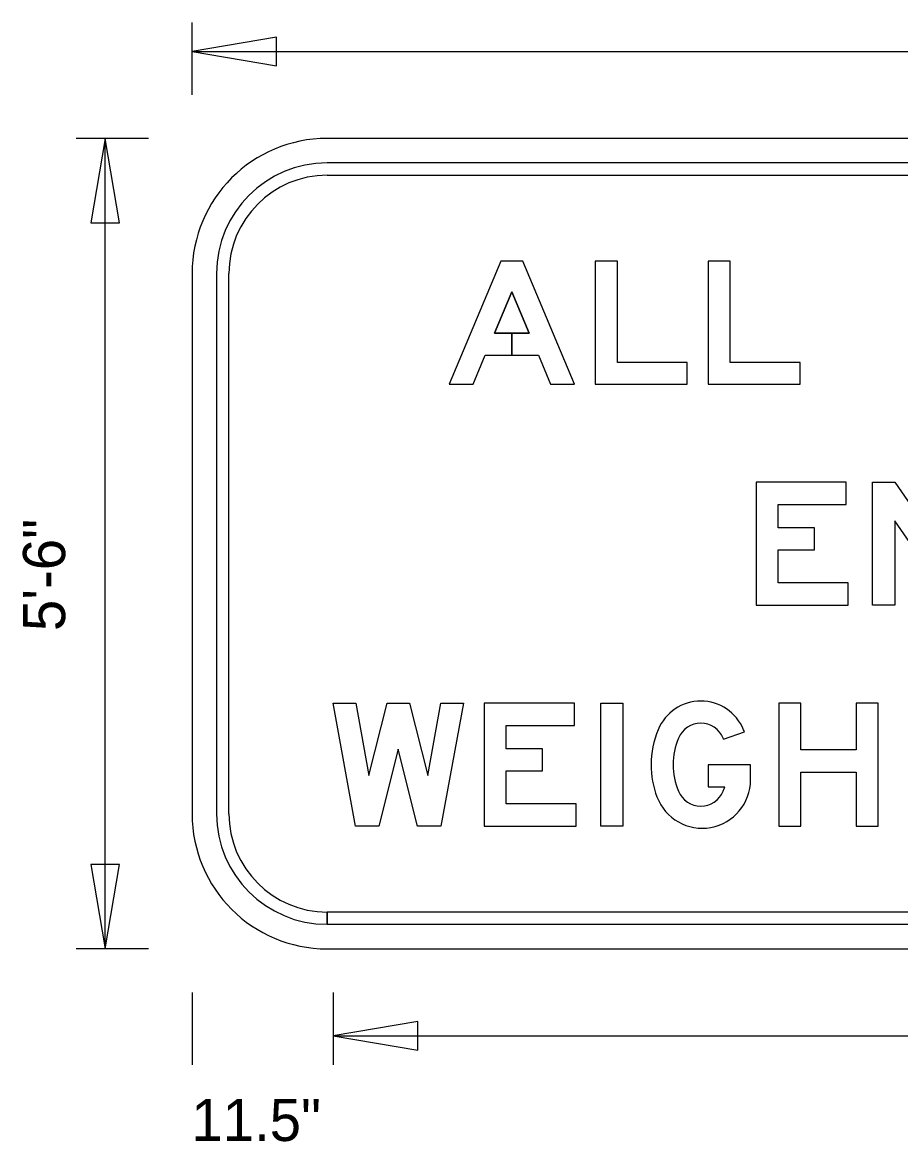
# Model space of a CAD drawing. Extents: x 0 to 770, y 0 to 495.
# Drawn here: x 7.2 to 80.1, y 381.9 to 474.8 of the extents above; entities that cross this region are included whole.
import ezdxf

# ---------------------------------------------------------------- set-up
doc = ezdxf.new("R2010")
doc.units = 0
for name, color, linetype in [('Dimension', 7, 'Continuous'), ('GSBWFill', 7, 'Continuous'), ('GSColorFill', 7, 'Continuous'), ('GSDims', 7, 'Continuous'), ('GSOutline', 7, 'Continuous'), ('TextStructures', 7, 'Continuous')]:
    doc.layers.add(name, color=color, linetype=linetype)

msp = doc.modelspace()

# ---------------------------------------------------------------- linework, layer by layer
at = {"layer": 'Dimension'}
for points in [[(21.25, 472.405), (28.266, 471.216), (28.266, 473.594)], [(14.025, 465.181), (12.837, 458.164), (15.214, 458.164)], [(14.025, 397.907), (15.214, 404.924), (12.837, 404.924)], [(32.972, 390.683), (39.988, 389.494), (39.988, 391.871)]]:
    msp.add_lwpolyline(points, close=True, dxfattribs=at)
at = {"layer": 'GSBWFill'}
for p, q in [((150.701, 465.181), (32.462, 465.181)), ((150.701, 463.142), (32.462, 463.142)), ((32.462, 462.123), (150.701, 462.123)), ((21.25, 453.969), (21.25, 409.119)), ((23.288, 453.969), (23.288, 409.119)), ((24.308, 409.119), (24.308, 453.969)), ((65.393, 415.305), (67.121, 415.923)), ((67.628, 411.935), (67.628, 413.196)), ((32.462, 399.946), (32.462, 400.965)), ((150.701, 400.965), (32.472, 400.965)), ((32.472, 400.965), (32.472, 399.946)), ((32.472, 399.946), (150.701, 399.946)), ((32.462, 397.907), (150.701, 397.907))]:
    msp.add_line(p, q, dxfattribs=at)
for points in [[(49.234, 449.025), (47.803, 449.025), (47.803, 447.19), (50.005, 447.19), (51.011, 444.795), (53.001, 444.795), (48.72, 454.988), (46.885, 454.988), (42.604, 444.795), (44.594, 444.795), (45.6, 447.19), (47.802, 447.19), (47.802, 449.025), (46.371, 449.025), (47.802, 452.434)], [(62.378, 444.795), (62.378, 446.579), (56.568, 446.579), (56.568, 454.988), (54.734, 454.988), (54.734, 444.795)], [(71.756, 444.795), (71.756, 446.579), (65.946, 446.579), (65.946, 454.988), (64.111, 454.988), (64.111, 444.795)], [(75.731, 428.282), (69.921, 428.282), (69.921, 431.024), (72.928, 431.024), (72.928, 432.859), (69.921, 432.859), (69.921, 434.806), (75.578, 434.806), (75.578, 436.64), (68.087, 436.64), (68.087, 426.447), (75.731, 426.447)], [(86.026, 436.64), (86.026, 426.447), (84.446, 426.447), (79.605, 433.43), (79.605, 426.447), (77.77, 426.447), (77.77, 436.64), (79.611, 436.64), (84.192, 430.035), (84.192, 436.64)], [(38.374, 414.471), (36.768, 408.1), (34.832, 408.1), (32.972, 418.293), (34.837, 418.293), (35.932, 412.29), (37.445, 418.293), (39.303, 418.293), (40.816, 412.29), (41.911, 418.293), (43.776, 418.293), (41.916, 408.1), (39.979, 408.1)], [(53.154, 409.935), (47.344, 409.935), (47.344, 412.676), (50.351, 412.676), (50.351, 414.511), (47.344, 414.511), (47.344, 416.458), (53.001, 416.458), (53.001, 418.293), (45.509, 418.293), (45.509, 408.1), (53.154, 408.1)], [(55.192, 408.1), (55.192, 418.293), (57.027, 418.293), (57.027, 408.1)], [(76.394, 414.42), (71.807, 414.42), (71.807, 418.293), (69.972, 418.293), (69.972, 408.1), (71.807, 408.1), (71.807, 412.585), (76.394, 412.585), (76.394, 408.1), (78.229, 408.1), (78.229, 418.293), (76.394, 418.293)]]:
    msp.add_lwpolyline(points, close=True, dxfattribs=at)
msp.add_lwpolyline([(67.628, 413.196), (64.111, 413.196), (64.111, 411.362), (65.493, 411.362)], dxfattribs=at)
for centre, radius, start, end in [((32.462, 453.969), 11.212, 90, 180), ((32.462, 453.969), 9.174, 90, 180), ((32.462, 453.969), 8.154, 90, 180), ((32.462, 409.119), 11.212, 180, 270), ((32.462, 409.119), 9.174, 180, 270), ((32.462, 409.119), 8.154, 180, 270)]:
    msp.add_arc(centre, radius, start, end, dxfattribs=at)
for centre, major_axis, start_param, end_param in [((63.5, 414.627), (0, 3.845), 5.10379, 7.46258), ((63.5, 414.627), (0, 2.01), 5.10379, 7.46258), ((66.965, 413.196), (0, 7.594), 1.179395, 1.570796), ((66.965, 413.196), (0, 5.759), 1.179395, 1.570796), ((60.034, 413.196), (0, 5.759), 5.087148, 5.10379), ((60.034, 413.196), (0, 7.594), 5.07965, 5.10379), ((66.965, 413.196), (0, 7.594), 1.570796, 1.930863), ((66.965, 413.196), (0, 5.759), 1.570796, 1.962198), ((63.614, 411.935), (0, 4.013), 1.930863, 4.712389), ((63.5, 411.766), (0, 2.01), 1.962198, 4.320988), ((60.034, 413.196), (0, 5.759), 4.320988, 4.388154)]:
    msp.add_ellipse(centre, major_axis=major_axis, ratio=0.999994, start_param=start_param, end_param=end_param, dxfattribs=at)
at = {"layer": 'GSColorFill'}
for p, q in [((65.393, 415.305), (67.121, 415.923)), ((67.628, 411.935), (67.628, 413.196))]:
    msp.add_line(p, q, dxfattribs=at)
for points in [[(49.234, 449.025), (47.803, 449.025), (47.803, 447.19), (50.005, 447.19), (51.011, 444.795), (53.001, 444.795), (48.72, 454.988), (46.885, 454.988), (42.604, 444.795), (44.594, 444.795), (45.6, 447.19), (47.802, 447.19), (47.802, 449.025), (46.371, 449.025), (47.802, 452.434)], [(62.378, 444.795), (62.378, 446.579), (56.568, 446.579), (56.568, 454.988), (54.734, 454.988), (54.734, 444.795)], [(71.756, 444.795), (71.756, 446.579), (65.946, 446.579), (65.946, 454.988), (64.111, 454.988), (64.111, 444.795)], [(75.731, 428.282), (69.921, 428.282), (69.921, 431.024), (72.928, 431.024), (72.928, 432.859), (69.921, 432.859), (69.921, 434.806), (75.578, 434.806), (75.578, 436.64), (68.087, 436.64), (68.087, 426.447), (75.731, 426.447)], [(86.026, 436.64), (86.026, 426.447), (84.446, 426.447), (79.605, 433.43), (79.605, 426.447), (77.77, 426.447), (77.77, 436.64), (79.611, 436.64), (84.192, 430.035), (84.192, 436.64)], [(38.374, 414.471), (36.768, 408.1), (34.832, 408.1), (32.972, 418.293), (34.837, 418.293), (35.932, 412.29), (37.445, 418.293), (39.303, 418.293), (40.816, 412.29), (41.911, 418.293), (43.776, 418.293), (41.916, 408.1), (39.979, 408.1)], [(53.154, 409.935), (47.344, 409.935), (47.344, 412.676), (50.351, 412.676), (50.351, 414.511), (47.344, 414.511), (47.344, 416.458), (53.001, 416.458), (53.001, 418.293), (45.509, 418.293), (45.509, 408.1), (53.154, 408.1)], [(55.192, 408.1), (55.192, 418.293), (57.027, 418.293), (57.027, 408.1)], [(76.394, 414.42), (71.807, 414.42), (71.807, 418.293), (69.972, 418.293), (69.972, 408.1), (71.807, 408.1), (71.807, 412.585), (76.394, 412.585), (76.394, 408.1), (78.229, 408.1), (78.229, 418.293), (76.394, 418.293)]]:
    msp.add_lwpolyline(points, close=True, dxfattribs=at)
msp.add_lwpolyline([(67.628, 413.196), (64.111, 413.196), (64.111, 411.362), (65.493, 411.362)], dxfattribs=at)
for centre, major_axis, start_param, end_param in [((63.5, 414.627), (0, 3.845), 5.10379, 7.46258), ((63.5, 414.627), (0, 2.01), 5.10379, 7.46258), ((66.965, 413.196), (0, 7.594), 1.179395, 1.570796), ((66.965, 413.196), (0, 5.759), 1.179395, 1.570796), ((60.034, 413.196), (0, 5.759), 5.087148, 5.10379), ((60.034, 413.196), (0, 7.594), 5.07965, 5.10379), ((66.965, 413.196), (0, 7.594), 1.570796, 1.930863), ((66.965, 413.196), (0, 5.759), 1.570796, 1.962198), ((63.614, 411.935), (0, 4.013), 1.930863, 4.712389), ((63.5, 411.766), (0, 2.01), 1.962198, 4.320988), ((60.034, 413.196), (0, 5.759), 4.320988, 4.388154)]:
    msp.add_ellipse(centre, major_axis=major_axis, ratio=0.999994, start_param=start_param, end_param=end_param, dxfattribs=at)
at = {"layer": 'GSDims'}
for p, q in [((21.25, 468.793), (21.25, 474.813)), ((21.25, 472.405), (161.913, 472.405)), ((17.637, 465.181), (11.617, 465.181)), ((14.025, 397.907), (14.025, 465.181)), ((17.637, 397.907), (11.617, 397.907)), ((21.25, 394.295), (21.25, 388.275)), ((32.972, 394.295), (32.972, 388.275)), ((32.972, 394.295), (32.972, 388.275)), ((32.972, 390.683), (150.191, 390.683))]:
    msp.add_line(p, q, dxfattribs=at)
at = {"layer": 'GSOutline'}
for p, q in [((65.393, 415.305), (67.121, 415.923)), ((67.628, 411.935), (67.628, 413.196))]:
    msp.add_line(p, q, dxfattribs=at)
for points in [[(45.6, 447.19), (50.005, 447.19), (51.011, 444.795), (53.001, 444.795), (48.72, 454.988), (46.885, 454.988), (42.604, 444.795), (44.594, 444.795)], [(62.378, 444.795), (62.378, 446.579), (56.568, 446.579), (56.568, 454.988), (54.734, 454.988), (54.734, 444.795)], [(71.756, 444.795), (71.756, 446.579), (65.946, 446.579), (65.946, 454.988), (64.111, 454.988), (64.111, 444.795)], [(49.234, 449.025), (47.802, 452.434), (46.371, 449.025)], [(75.731, 428.282), (69.921, 428.282), (69.921, 431.024), (72.928, 431.024), (72.928, 432.859), (69.921, 432.859), (69.921, 434.806), (75.578, 434.806), (75.578, 436.64), (68.087, 436.64), (68.087, 426.447), (75.731, 426.447)], [(86.026, 436.64), (86.026, 426.447), (84.446, 426.447), (79.605, 433.43), (79.605, 426.447), (77.77, 426.447), (77.77, 436.64), (79.611, 436.64), (84.192, 430.035), (84.192, 436.64)], [(38.374, 414.471), (36.768, 408.1), (34.832, 408.1), (32.972, 418.293), (34.837, 418.293), (35.932, 412.29), (37.445, 418.293), (39.303, 418.293), (40.816, 412.29), (41.911, 418.293), (43.776, 418.293), (41.916, 408.1), (39.979, 408.1)], [(53.154, 409.935), (47.344, 409.935), (47.344, 412.676), (50.351, 412.676), (50.351, 414.511), (47.344, 414.511), (47.344, 416.458), (53.001, 416.458), (53.001, 418.293), (45.509, 418.293), (45.509, 408.1), (53.154, 408.1)], [(55.192, 408.1), (55.192, 418.293), (57.027, 418.293), (57.027, 408.1)], [(76.394, 414.42), (71.807, 414.42), (71.807, 418.293), (69.972, 418.293), (69.972, 408.1), (71.807, 408.1), (71.807, 412.585), (76.394, 412.585), (76.394, 408.1), (78.229, 408.1), (78.229, 418.293), (76.394, 418.293)]]:
    msp.add_lwpolyline(points, close=True, dxfattribs=at)
msp.add_lwpolyline([(67.628, 413.196), (64.111, 413.196), (64.111, 411.362), (65.493, 411.362)], dxfattribs=at)
for centre, major_axis, start_param, end_param in [((63.5, 414.627), (0, 3.845), 5.10379, 7.46258), ((63.5, 414.627), (0, 2.01), 5.10379, 7.46258), ((66.965, 413.196), (0, 7.594), 1.179395, 1.570796), ((66.965, 413.196), (0, 5.759), 1.179395, 1.570796), ((60.034, 413.196), (0, 5.759), 5.087148, 5.10379), ((60.034, 413.196), (0, 7.594), 5.07965, 5.10379), ((66.965, 413.196), (0, 7.594), 1.570796, 1.930863), ((66.965, 413.196), (0, 5.759), 1.570796, 1.962198), ((63.614, 411.935), (0, 4.013), 1.930863, 4.712389), ((63.5, 411.766), (0, 2.01), 1.962198, 4.320988), ((60.034, 413.196), (0, 5.759), 4.320988, 4.388154)]:
    msp.add_ellipse(centre, major_axis=major_axis, ratio=0.999994, start_param=start_param, end_param=end_param, dxfattribs=at)

# ---------------------------------------------------------------- texts
at = {"layer": 'TextStructures'}
msp.add_text('5\'-6"', height=3.5, rotation=90, dxfattribs=at).set_placement((10.706, 424.284))
msp.add_text('11.5"', height=3.5, dxfattribs=at).set_placement((21.188, 381.958))

doc.saveas('drawing.dxf')
